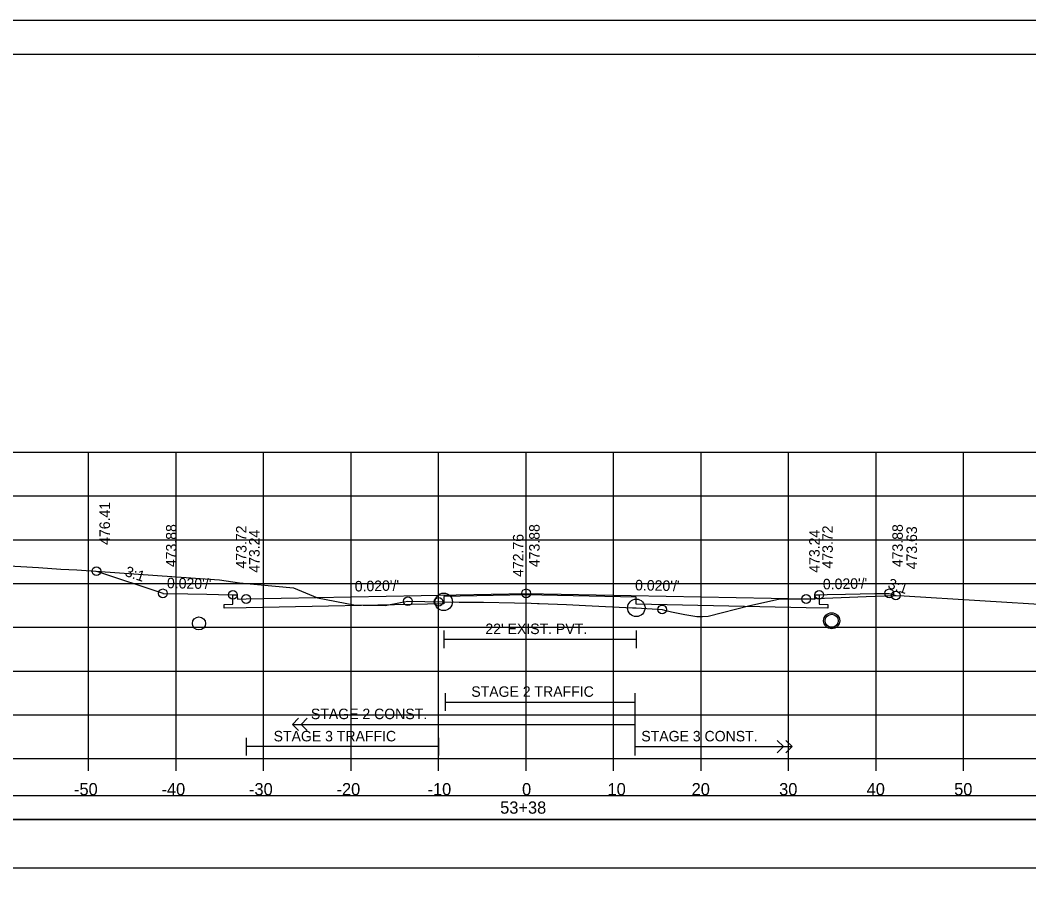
# Model space of a CAD drawing. Extents: x 1371057 to 1372761, y 380005 to 390517.
# Drawn here: x 1371503.1 to 1371618.3, y 383533.7 to 383631.8 of the extents above; entities that cross this region are included whole.
import ezdxf

# ---------------------------------------------------------------- set-up
doc = ezdxf.new("R2010")
doc.units = 0
for name, color, linetype in [('R_Alt Surface', 7, 'Continuous'), ('R_Axis', 7, 'Continuous'), ('R_Axis Annot', 7, 'Continuous'), ('R_Border', 7, 'Continuous'), ('R_Detour', 7, 'Continuous'), ('R_Dimension', 7, 'Continuous'), ('R_Exist Surface', 7, 'Continuous'), ('R_Fin Surface', 7, 'Continuous'), ('R_Grid', 7, 'Continuous'), ('R_No Plot', 7, 'Continuous'), ('R_Striping', 7, 'Continuous'), ('R_Water', 7, 'Continuous'), ('R_Xsect Elev', 7, 'Continuous'), ('R_Xsect Slope', 7, 'Continuous')]:
    doc.layers.add(name, color=color, linetype=linetype)

msp = doc.modelspace()

# ---------------------------------------------------------------- linework, layer by layer
at = {"layer": 'R_Alt Surface'}
for points in [[(1371594.37, 383566.18), (1371594.37, 383565.1), (1371595.37, 383565.08), (1371595.37, 383564.65), (1371592.87, 383564.7), (1371573.46, 383565.09), (1371573.46, 383565.92), (1371560.87, 383566.17), (1371551.46, 383565.98), (1371551.46, 383565.15), (1371528.87, 383564.7), (1371526.37, 383564.65), (1371526.37, 383565.08), (1371527.37, 383565.1), (1371527.37, 383566.18)], [(1371594.37, 383566.18), (1371594.37, 383565.1), (1371595.37, 383565.08), (1371595.37, 383564.65), (1371592.87, 383564.7), (1371573.46, 383565.09), (1371573.46, 383565.92), (1371560.87, 383566.17), (1371551.46, 383565.98), (1371551.46, 383565.15), (1371528.87, 383564.7), (1371526.37, 383564.65), (1371526.37, 383565.08), (1371527.37, 383565.1), (1371527.37, 383566.18)], [(1371551.46, 383562.09), (1371551.46, 383560.09)], [(1371573.46, 383562.09), (1371573.46, 383560.09)], [(1371551.46, 383561.09), (1371573.46, 383561.09)]]:
    msp.add_lwpolyline(points, dxfattribs=at)
at = {"layer": 'R_Axis'}
for p, q in [((1371410.87, 383547.47), (1371710.87, 383547.47)), ((1371510.87, 383546.07), (1371510.87, 383547.47)), ((1371520.87, 383546.07), (1371520.87, 383547.47)), ((1371530.87, 383546.07), (1371530.87, 383547.47)), ((1371540.87, 383546.07), (1371540.87, 383547.47)), ((1371550.87, 383546.07), (1371550.87, 383547.47)), ((1371560.87, 383546.07), (1371560.87, 383547.47)), ((1371570.87, 383546.07), (1371570.87, 383547.47)), ((1371580.87, 383546.07), (1371580.87, 383547.47)), ((1371590.87, 383546.07), (1371590.87, 383547.47)), ((1371600.87, 383546.07), (1371600.87, 383547.47)), ((1371610.87, 383546.07), (1371610.87, 383547.47))]:
    msp.add_line(p, q, dxfattribs=at)
at = {"layer": 'R_Border'}
for p, q in [((1371402.87, 383627.93), (1371719.05, 383627.93)), ((1371555.39, 383627.67), (1371555.39, 383627.67)), ((1371555.39, 383627.67), (1371555.39, 383627.67))]:
    msp.add_line(p, q, dxfattribs=at)
at = {"layer": 'R_Detour'}
msp.add_lwpolyline([(1371407.72, 383540.51), (1371714.03, 383540.51), (1371714.03, 383543.22), (1371407.72, 383543.22)], close=True, dxfattribs=at)
at = {"layer": 'R_Dimension'}
msp.add_lwpolyline([(1371407.72, 383534.99), (1371714.03, 383534.99), (1371714.03, 383540.51), (1371407.72, 383540.51)], close=True, dxfattribs=at)
at = {"layer": 'R_Exist Surface'}
msp.add_lwpolyline([(1371492.97, 383569.98), (1371505.14, 383569.29), (1371507.71, 383569.12), (1371509.55, 383569.03), (1371525.28, 383567.93), (1371525.84, 383567.89), (1371528.11, 383567.53), (1371534.3, 383566.97), (1371537.02, 383565.82), (1371541.17, 383565.02), (1371542.26, 383564.98), (1371544.75, 383564.94), (1371546.53, 383565.28), (1371547.37, 383565.44), (1371549.3, 383565.41), (1371551.46, 383565.37), (1371553.22, 383565.35), (1371555.99, 383565.33), (1371559.54, 383565.26), (1371561.46, 383565.21), (1371562.16, 383565.18), (1371562.35, 383565.17), (1371565.49, 383565.05), (1371567.66, 383564.95), (1371573.04, 383564.7), (1371573.46, 383564.68), (1371575.9, 383564.54), (1371576.42, 383564.51), (1371576.7, 383564.42), (1371577.5, 383564.22), (1371579, 383563.91), (1371580.39, 383563.68), (1371581.04, 383563.7), (1371581.69, 383563.74), (1371586.43, 383564.95), (1371589.71, 383565.68), (1371593.07, 383565.72), (1371599.72, 383565.98), (1371602.86, 383566.1), (1371604.07, 383566.06), (1371621.35, 383565)], dxfattribs=at)
at = {"layer": 'R_Fin Surface'}
msp.add_lwpolyline([(1371511.77, 383568.88), (1371519.35, 383566.35), (1371519.37, 383566.34), (1371519.39, 383566.34), (1371522.21, 383566.29), (1371524.37, 383566.24), (1371525.73, 383566.22), (1371527.36, 383566.18), (1371527.37, 383566.18), (1371527.76, 383566.18), (1371527.87, 383566.18), (1371527.87, 383566.06), (1371527.88, 383565.68), (1371527.88, 383565.68), (1371528.87, 383565.7), (1371528.9, 383565.7), (1371560.87, 383566.34), (1371592.86, 383565.7), (1371592.87, 383565.7), (1371593.09, 383565.7), (1371593.87, 383565.68), (1371593.87, 383565.87), (1371593.87, 383566.18), (1371594.16, 383566.18), (1371594.37, 383566.18), (1371595.28, 383566.2), (1371597.36, 383566.24), (1371597.37, 383566.24), (1371600.72, 383566.31), (1371602.37, 383566.34), (1371602.66, 383566.25), (1371603.12, 383566.09), (1371603.12, 383566.09)], dxfattribs=at)
at = {"layer": 'R_Grid'}
for p, q in [((1371410.87, 383582.47), (1371710.87, 383582.47)), ((1371510.87, 383547.47), (1371510.87, 383582.47)), ((1371520.87, 383547.47), (1371520.87, 383582.47)), ((1371530.87, 383547.47), (1371530.87, 383582.47)), ((1371540.87, 383547.47), (1371540.87, 383582.47)), ((1371550.87, 383547.47), (1371550.87, 383582.47)), ((1371560.87, 383547.47), (1371560.87, 383582.47)), ((1371570.87, 383547.47), (1371570.87, 383582.47)), ((1371580.87, 383547.47), (1371580.87, 383582.47)), ((1371590.87, 383547.47), (1371590.87, 383582.47)), ((1371600.87, 383547.47), (1371600.87, 383582.47)), ((1371610.87, 383547.47), (1371610.87, 383582.47)), ((1371410.87, 383577.47), (1371710.87, 383577.47)), ((1371410.87, 383572.47), (1371710.87, 383572.47)), ((1371410.87, 383567.47), (1371710.87, 383567.47)), ((1371410.87, 383562.47), (1371710.87, 383562.47)), ((1371410.87, 383557.47), (1371710.87, 383557.47)), ((1371410.87, 383552.47), (1371710.87, 383552.47)), ((1371410.87, 383547.47), (1371710.87, 383547.47))]:
    msp.add_line(p, q, dxfattribs=at)
at = {"layer": 'R_No Plot'}
msp.add_line((1371390.47, 383631.82), (1371723.8, 383631.82), dxfattribs=at)
for points in [[(1371390.46, 383631.82), (1371723.8, 383631.82), (1371723.8, 383418.48), (1371390.46, 383418.48)], [(1371636.79, 383627.93), (1371656.41, 383627.93), (1371656.41, 383618.05), (1371672.52, 383618.05), (1371695.72, 383618.05), (1371695.84, 383589.89), (1371719.05, 383589.89), (1371719.05, 383422.47), (1371402.87, 383422.47), (1371402.87, 383627.93)]]:
    msp.add_lwpolyline(points, close=True, dxfattribs=at)
for centre, radius in [((1371511.77, 383568.88), 0.5), ((1371519.37, 383566.34), 0.5), ((1371527.37, 383566.18), 0.5), ((1371560.87, 383566.34), 0.5), ((1371594.37, 383566.18), 0.5), ((1371602.37, 383566.34), 0.5), ((1371603.12, 383566.09), 0.5), ((1371528.87, 383565.7), 0.5), ((1371547.37, 383565.44), 0.5), ((1371550.87, 383565.38), 0.5), ((1371551.46, 383565.37), 1), ((1371573.46, 383564.68), 1), ((1371592.87, 383565.7), 0.5), ((1371576.42, 383564.51), 0.5), ((1371595.79, 383563.21), 0.917)]:
    msp.add_circle(centre, radius, dxfattribs=at)
at = {"layer": 'R_Striping'}
for p, q in [((1371551.64, 383554.92), (1371551.64, 383552.92)), ((1371551.64, 383553.92), (1371573.28, 383553.92)), ((1371573.28, 383554.92), (1371573.28, 383547.83)), ((1371534.16, 383551.37), (1371534.86, 383552.08)), ((1371535.16, 383551.37), (1371535.86, 383552.08)), ((1371534.16, 383551.37), (1371573.28, 383551.37)), ((1371534.86, 383550.67), (1371534.16, 383551.37)), ((1371535.86, 383550.67), (1371535.16, 383551.37)), ((1371528.87, 383549.83), (1371528.87, 383547.83)), ((1371550.87, 383549.83), (1371550.87, 383547.83)), ((1371590.28, 383548.83), (1371589.57, 383549.54)), ((1371591.28, 383548.83), (1371590.57, 383549.54)), ((1371550.87, 383548.83), (1371528.87, 383548.83)), ((1371573.28, 383548.83), (1371591.28, 383548.83)), ((1371573.31, 383548.83), (1371583.31, 383548.83)), ((1371589.57, 383548.12), (1371590.28, 383548.83)), ((1371590.57, 383548.12), (1371591.28, 383548.83))]:
    msp.add_line(p, q, dxfattribs=at)
at = {"layer": 'R_Water'}
for centre in [(1371523.49, 383562.91), (1371595.79, 383563.21)]:
    msp.add_circle(centre, 0.75, dxfattribs=at)
at = {"layer": 'R_Xsect Elev'}
msp.add_line((1371560.87, 383565.22), (1371560.87, 383575.22), dxfattribs=at)

# ---------------------------------------------------------------- texts
at = {"layer": 'R_Axis Annot'}
for s, p in [('-50', (1371509.21, 383543.27)), ('-40', (1371519.21, 383543.27)), ('-30', (1371529.21, 383543.27)), ('-20', (1371539.21, 383543.27)), ('-10', (1371549.61, 383543.27)), ('0', (1371560.41, 383543.27)), ('10', (1371570.18, 383543.27)), ('20', (1371579.79, 383543.27)), ('30', (1371589.79, 383543.27)), ('40', (1371599.79, 383543.27)), ('50', (1371609.79, 383543.27)), ('53+38', (1371557.91, 383541.17))]:
    msp.add_text(s, height=1.4, dxfattribs=at).set_placement(p)
at = {"layer": 'R_Striping'}
for s, p in [('STAGE 2 TRAFFIC', (1371554.61, 383554.52)), ('STAGE 2 CONST.', (1371536.28, 383551.97)), ('STAGE 3 TRAFFIC', (1371532.02, 383549.43)), ('STAGE 3 CONST.', (1371574.04, 383549.43))]:
    msp.add_text(s, height=1.2, dxfattribs=at).set_placement(p)
at = {"layer": 'R_Water'}
msp.add_text("22' EXIST. PVT.", height=1.2, dxfattribs=at).set_placement((1371556.22, 383561.69))
at = {"layer": 'R_Xsect Elev'}
for s, p in [('476.41', (1371513.32, 383571.88)), ('473.88', (1371520.92, 383569.34)), ('473.72', (1371528.92, 383569.18)), ('473.24', (1371530.42, 383568.7)), ('473.88', (1371562.42, 383569.34)), ('473.24', (1371594.42, 383568.7)), ('473.72', (1371595.92, 383569.18)), ('473.88', (1371603.92, 383569.34)), ('473.63', (1371605.54, 383569.09)), ('472.76', (1371560.57, 383568.22))]:
    msp.add_text(s, height=1.2, rotation=90, dxfattribs=at).set_placement(p)
at = {"layer": 'R_Xsect Slope'}
for s, rotation, p in [('3:1', 341.5713, (1371514.94, 383568.35)), ("0.020'/'", 358.8542, (1371519.82, 383566.93)), ("0.020'/'", 1.1457, (1371541.3, 383566.55)), ("0.020'/'", 358.8542, (1371573.32, 383566.69)), ("0.020'/'", 1.1458, (1371594.8, 383566.79)), ('3:1', 341.5306, (1371602.12, 383566.96))]:
    msp.add_text(s, height=1.2, rotation=rotation, dxfattribs=at).set_placement(p)

doc.saveas('drawing.dxf')
